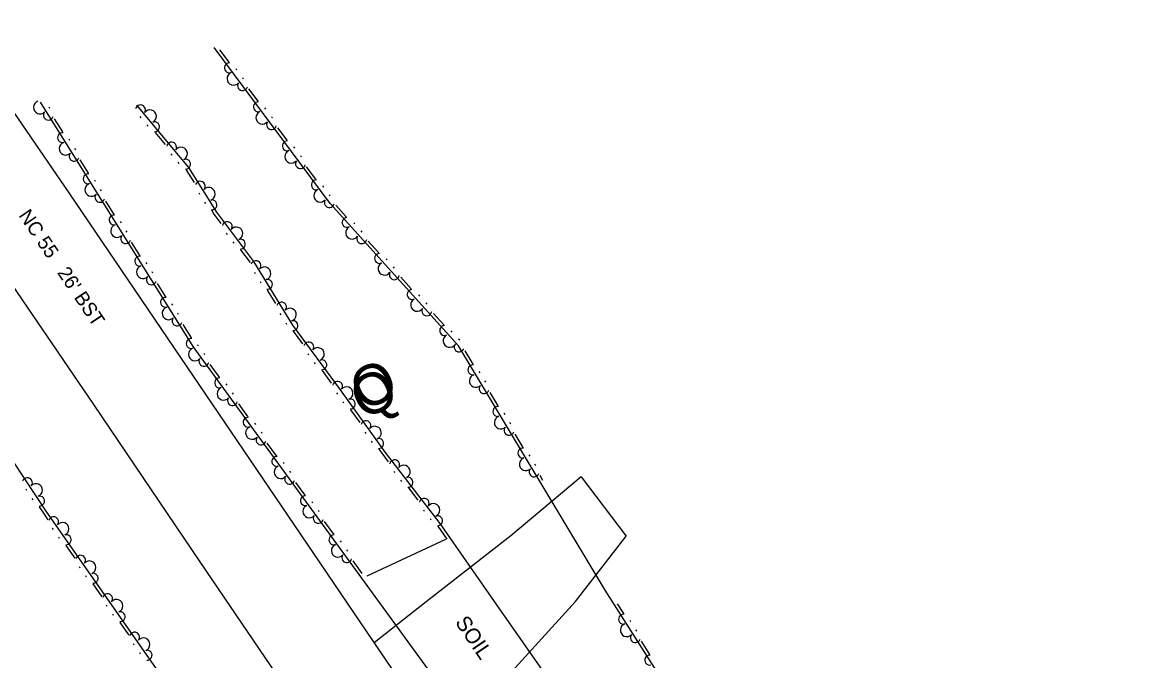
# Model space of a CAD drawing. Extents: x 2030130 to 2036320, y 723205 to 762423.
# Drawn here: x 2032827.6 to 2033121.2, y 761944.8 to 762111.9 of the extents above; entities that cross this region are included whole.
import ezdxf

# ---------------------------------------------------------------- set-up
doc = ezdxf.new("R2010")
doc.units = 0
for name, color, linetype in [('Draft_Station Cardinal Points', 7, 'Continuous'), ('Draft_Station Labels Major', 7, 'Continuous'), ('Draft_Station Tics Major', 7, 'Continuous'), ('Old_Level_15', 7, 'Continuous'), ('Old_Level_23', 7, 'Continuous')]:
    doc.layers.add(name, color=color, linetype=linetype)

msp = doc.modelspace()

# ---------------------------------------------------------------- linework, layer by layer
at = {"layer": 'Draft_Station Labels Major'}
for p, q in [((2032973.91, 761992.92), (2032985.71, 761977.44)), ((2032933.32, 761960.17), (2032919.77, 761949.48))]:
    msp.add_line(p, q, dxfattribs=at)
for points in [[(2032982.25, 761857.44), (2032953.98, 761899.13), (2032895.43, 761985.31), (2032867.48, 762026.64), (2032839.86, 762067.31), (2032810.94, 762109.31), (2032783.52, 762149.89), (2032755.69, 762190.54), (2032727.21, 762232.52), (2032699.29, 762273.24), (2032670.84, 762315.05), (2032643.99, 762354.39), (2032615.89, 762395.7), (2032597.19, 762422.99)], [(2032578.53, 762404.38), (2032622.03, 762340.46), (2032649.81, 762299.71), (2032677.92, 762258.76), (2032706.15, 762217.66), (2032734.05, 762176.43), (2032762.1, 762135.36), (2032790.25, 762094.19), (2032818.14, 762052.99), (2032846.2, 762011.84), (2032874.09, 761970.67), (2032902.04, 761929.59), (2032931.85, 761885.67), (2032959.96, 761844.28)], [(2032973.91, 761992.92), (2032955.52, 761977.52), (2032933.32, 761960.17)], [(2032951.33, 761937.1), (2032972.48, 761960.26), (2032985.71, 761977.44)]]:
    msp.add_lwpolyline(points, dxfattribs=at)
at = {"layer": 'Draft_Station Tics Major'}
msp.add_line((2032938.43, 761976.49), (2032917.81, 761966.94), dxfattribs=at)
for points in [[(2033121.18, 761743.95), (2033080.74, 761813.47), (2033046.05, 761862.02), (2033015.65, 761907.58), (2032980.17, 761963.3), (2032941.81, 762027.2), (2032908.21, 762064.45), (2032877.87, 762105.34)], [(2032881.77, 762101.46), (2032879.32, 762104.75)], [(2032883.81, 762099.4), (2032883.56, 762099.72)], [(2032885.52, 762097.09), (2032885.27, 762097.42)], [(2032889.34, 762091.25), (2032886.9, 762094.54)], [(2033107.4, 761688.4), (2033049.51, 761771.21), (2032985.52, 761870.07), (2032934.46, 761941.71), (2032872.35, 762027.01), (2032832.35, 762090.98)], [(2032834.82, 762089.34), (2032834.61, 762089.69)], [(2032857.5, 762090.26), (2032871.14, 762073.87), (2032878.45, 762062.18), (2032888.1, 762049.28), (2032898.38, 762032.64), (2032910.79, 762015.75), (2032922.64, 761999.26), (2032936.88, 761980.71), (2032951.77, 761959.4), (2032965.55, 761939.68), (2032981.68, 761910.94), (2032991.86, 761892.63), (2033007.03, 761869.02), (2033018.32, 761853.44), (2033031.66, 761833.88), (2033047.89, 761810.12), (2033068.77, 761781.86), (2033086.33, 761752.31)], [(2032891.38, 762089.19), (2032891.14, 762089.52)], [(2032838.17, 762083.21), (2032836, 762086.69)], [(2032858.39, 762087.27), (2032858.65, 762086.95)], [(2032860.22, 762085.06), (2032860.49, 762084.74)], [(2032893.09, 762086.88), (2032892.85, 762087.21)], [(2032862.38, 762083.11), (2032865, 762079.96)], [(2032896.92, 762081.04), (2032894.48, 762084.33)], [(2032840.04, 762080.99), (2032839.83, 762081.34)], [(2032841.57, 762078.56), (2032841.35, 762078.91)], [(2032898.96, 762078.97), (2032898.72, 762079.3)], [(2032844.92, 762072.43), (2032842.74, 762075.91)], [(2032866.52, 762077.49), (2032866.78, 762077.18)], [(2032900.67, 762076.67), (2032900.43, 762077)], [(2032868.36, 762075.29), (2032868.62, 762074.97)], [(2032870.44, 762073.43), (2032872.62, 762069.96)], [(2032904.49, 762070.83), (2032902.05, 762074.12)], [(2032846.79, 762070.21), (2032846.57, 762070.56)], [(2032848.31, 762067.78), (2032848.09, 762068.13)], [(2032873.79, 762067.31), (2032874.01, 762066.96)], [(2032906.53, 762068.77), (2032906.29, 762069.1)], [(2032851.66, 762061.65), (2032849.48, 762065.13)], [(2032875.32, 762064.87), (2032875.53, 762064.52)], [(2032908.24, 762066.46), (2032908, 762066.79)], [(2032912.42, 762061), (2032909.67, 762064.05)], [(2032877.19, 762062.66), (2032877.78, 762061.71), (2032879.61, 762059.26)], [(2032987.59, 761762.73), (2032957.8, 761805.4), (2032921.13, 761858.06), (2032890.88, 761904.34), (2032862.59, 761942.95), (2032834.05, 761983.65), (2032801.35, 762033.01), (2032781.96, 762059.34)], [(2032853.53, 762059.44), (2032853.31, 762059.78)], [(2032914.65, 762059.15), (2032914.37, 762059.45)], [(2032855.05, 762057), (2032854.83, 762057.35)], [(2032881, 762056.72), (2032881.24, 762056.39)], [(2032916.57, 762057.01), (2032916.3, 762057.32)], [(2032858.4, 762050.87), (2032856.22, 762054.35)], [(2032882.72, 762054.42), (2032882.96, 762054.09)], [(2032884.77, 762052.37), (2032887.22, 762049.08)], [(2032920.94, 762051.56), (2032918.19, 762054.61)], [(2032923.16, 762049.71), (2032922.89, 762050.01)], [(2032860.27, 762048.66), (2032860.05, 762049.01)], [(2032861.79, 762046.22), (2032861.57, 762046.57)], [(2032888.37, 762046.5), (2032888.58, 762046.15)], [(2032925.08, 762047.58), (2032924.81, 762047.88)], [(2032865.14, 762040.09), (2032862.96, 762043.57)], [(2032889.88, 762044.06), (2032890.09, 762043.71)], [(2032929.45, 762042.12), (2032926.7, 762045.17)], [(2032891.73, 762041.83), (2032893.89, 762038.34)], [(2032931.68, 762040.27), (2032931.4, 762040.57)], [(2032867.01, 762037.88), (2032866.79, 762038.23)], [(2032933.6, 762038.14), (2032933.33, 762038.44)], [(2032868.53, 762035.44), (2032868.31, 762035.79)], [(2032895.05, 762035.69), (2032895.26, 762035.34)], [(2032937.97, 762032.68), (2032935.22, 762035.73)], [(2032871.88, 762029.32), (2032869.7, 762032.79)], [(2032896.56, 762033.24), (2032896.77, 762032.9)], [(2032898.54, 762031.03), (2032900.97, 762027.72)], [(2032940.19, 762030.83), (2032939.92, 762031.13)], [(2032942.12, 762028.7), (2032941.84, 762029)], [(2032873.74, 762027.2), (2032873.5, 762027.53)], [(2032945.64, 762022.42), (2032943.52, 762025.94)], [(2032875.43, 762024.88), (2032875.19, 762025.21)], [(2032902.34, 762025.17), (2032902.59, 762024.83)], [(2032904.04, 762022.85), (2032904.29, 762022.52)], [(2032879.2, 762019), (2032876.79, 762022.31)], [(2032906.07, 762020.78), (2032908.5, 762017.48)], [(2032947.46, 762020.17), (2032947.25, 762020.52)], [(2032881.22, 762016.92), (2032880.98, 762017.25)], [(2032948.94, 762017.71), (2032948.73, 762018.06)], [(2032882.91, 762014.6), (2032882.67, 762014.93)], [(2032909.86, 762014.93), (2032910.1, 762014.6)], [(2032952.18, 762011.52), (2032950.07, 762015.04)], [(2032886.68, 762008.72), (2032884.27, 762012.04)], [(2032911.54, 762012.6), (2032911.78, 762012.27)], [(2032913.55, 762010.51), (2032915.94, 762007.18)], [(2032954.01, 762009.27), (2032953.8, 762009.62)], [(2032888.71, 762006.64), (2032888.46, 762006.97)], [(2032955.49, 762006.81), (2032955.28, 762007.16)], [(2032890.39, 762004.32), (2032890.15, 762004.65)], [(2032917.28, 762004.61), (2032917.52, 762004.28)], [(2032918.96, 762002.28), (2032919.2, 762001.94)], [(2032958.72, 762000.62), (2032956.61, 762004.14)], [(2032894.17, 761998.44), (2032891.75, 762001.76)], [(2032920.96, 762000.18), (2032921.98, 761998.77), (2032923.43, 761996.88)], [(2032896.19, 761996.37), (2032895.95, 761996.7)], [(2032960.55, 761998.37), (2032960.34, 761998.72)], [(2032897.88, 761994.05), (2032897.63, 761994.38)], [(2032924.86, 761994.35), (2032925.1, 761994.03)], [(2032962.03, 761995.91), (2032961.82, 761996.26)], [(2032901.65, 761988.17), (2032899.24, 761991.48)], [(2032926.61, 761992.07), (2032926.86, 761991.75)], [(2032963.91, 761991.99), (2032963.16, 761993.24)], [(2032828.81, 761989.33), (2032828.58, 761989.68)], [(2032928.68, 761990.05), (2032931.18, 761986.79)], [(2032830.4, 761986.94), (2032830.17, 761987.28)], [(2032834.41, 761981.71), (2032833.37, 761983.19), (2032832.1, 761985.12)], [(2032903.67, 761986.09), (2032903.43, 761986.42)], [(2032905.36, 761983.77), (2032905.12, 761984.1)], [(2032932.6, 761984.27), (2032932.85, 761983.94)], [(2032934.35, 761981.99), (2032934.6, 761981.67)], [(2032835.73, 761979.12), (2032835.49, 761979.46)], [(2032909.13, 761977.89), (2032906.72, 761981.2)], [(2032936.39, 761979.98), (2032938.74, 761976.62)], [(2032837.37, 761976.77), (2032837.14, 761977.11)], [(2032911.15, 761975.81), (2032910.91, 761976.14)], [(2032841.48, 761971.63), (2032839.12, 761974.99)], [(2032912.84, 761973.49), (2032912.6, 761973.82)], [(2032916.61, 761967.61), (2032914.2, 761970.93)], [(2032842.79, 761969.05), (2032842.55, 761969.38)], [(2032844.44, 761966.69), (2032844.2, 761967.03)], [(2032848.54, 761961.56), (2032846.18, 761964.92)], [(2032849.85, 761958.97), (2032849.62, 761959.31)], [(2032985.06, 761957.15), (2032983.43, 761959.71)], [(2032851.5, 761956.62), (2032851.26, 761956.96)], [(2032986.95, 761954.95), (2032986.73, 761955.29)], [(2032855.6, 761951.48), (2032853.25, 761954.84)], [(2032988.49, 761952.53), (2032988.27, 761952.87)], [(2032991.89, 761946.43), (2032989.69, 761949.89)], [(2032856.91, 761948.9), (2032856.68, 761949.23)], [(2032858.56, 761946.55), (2032858.33, 761946.88)]]:
    msp.add_lwpolyline(points, dxfattribs=at)
for centre, radius, start, end in [((2032881.84, 762099.98), 1.3, 87.344, 288.1405), ((2032882.89, 762097.18), 1.69, 112.5392, 320.6117), ((2032885.26, 762095.37), 1.3, 145.0104, 345.807), ((2032832.22, 762089.64), 1.69, 107.9852, 316.0577), ((2032889.42, 762089.77), 1.3, 87.344, 288.1405), ((2032834.43, 762087.64), 1.3, 140.4564, 341.253), ((2032858.55, 762089), 1.3, 328.2038, 169.0004), ((2032861.01, 762087.32), 1.69, 295.7326, 143.8051), ((2032890.47, 762086.98), 1.69, 112.5392, 320.6117), ((2032862.22, 762084.59), 1.3, 270.5374, 111.3339), ((2032892.84, 762085.16), 1.3, 145.0104, 345.807), ((2032838.13, 762081.73), 1.3, 82.79, 283.5865), ((2032838.96, 762078.86), 1.69, 107.9852, 316.0577), ((2032866.68, 762079.23), 1.3, 328.2038, 169.0004), ((2032869.15, 762077.54), 1.69, 295.7326, 143.8051), ((2032896.99, 762079.56), 1.3, 87.344, 288.1405), ((2032841.18, 762076.86), 1.3, 140.4564, 341.253), ((2032870.35, 762074.81), 1.3, 270.5374, 111.3339), ((2032898.05, 762076.77), 1.69, 112.5392, 320.6117), ((2032900.42, 762074.95), 1.3, 145.0104, 345.807), ((2032844.87, 762070.95), 1.3, 82.79, 283.5865), ((2032874.18, 762069), 1.3, 320.4692, 161.2658), ((2032904.57, 762069.35), 1.3, 87.344, 288.1405), ((2032845.7, 762068.08), 1.69, 107.9852, 316.0577), ((2032847.92, 762066.09), 1.3, 140.4564, 341.253), ((2032876.4, 762067), 1.69, 287.998, 136.0705), ((2032905.62, 762066.56), 1.69, 112.5392, 320.6117), ((2032877.23, 762064.13), 1.3, 262.8028, 103.5993), ((2032907.99, 762064.74), 1.3, 145.0104, 345.807), ((2032851.61, 762060.17), 1.3, 82.79, 283.5865), ((2032852.44, 762057.31), 1.69, 107.9852, 316.0577), ((2032881.25, 762058.44), 1.3, 325.2249, 166.0215), ((2032883.62, 762056.63), 1.69, 292.7537, 140.8262), ((2032912.63, 762059.54), 1.3, 92.823, 293.6195), ((2032913.95, 762056.86), 1.69, 118.0182, 326.0907), ((2032854.66, 762055.31), 1.3, 140.4564, 341.253), ((2032884.69, 762053.84), 1.3, 267.5584, 108.355), ((2032916.48, 762055.28), 1.3, 150.4894, 351.286), ((2032858.35, 762049.4), 1.3, 82.79, 283.5865), ((2032888.77, 762048.2), 1.3, 320.133, 160.9295), ((2032921.15, 762050.1), 1.3, 92.823, 293.6195), ((2032859.18, 762046.53), 1.69, 107.9852, 316.0577), ((2032890.97, 762046.19), 1.69, 287.6618, 135.7342), ((2032922.46, 762047.42), 1.69, 118.0182, 326.0907), ((2032925, 762045.84), 1.3, 150.4894, 351.286), ((2032861.4, 762044.53), 1.3, 140.4564, 341.253), ((2032891.78, 762043.31), 1.3, 262.4665, 103.2631), ((2032929.67, 762040.66), 1.3, 92.823, 293.6195), ((2032865.09, 762038.62), 1.3, 82.79, 283.5865), ((2032895.45, 762037.38), 1.3, 320.133, 160.9295), ((2032930.98, 762037.98), 1.69, 118.0182, 326.0907), ((2032865.92, 762035.75), 1.69, 107.9852, 316.0577), ((2032868.14, 762033.75), 1.3, 140.4564, 341.253), ((2032897.65, 762035.37), 1.69, 287.6618, 135.7342), ((2032933.51, 762036.4), 1.3, 150.4894, 351.286), ((2032898.48, 762032.5), 1.3, 267.0923, 107.8889), ((2032938.18, 762031.22), 1.3, 92.823, 293.6195), ((2032871.84, 762027.84), 1.3, 82.79, 283.5865), ((2032939.5, 762028.54), 1.69, 118.0182, 326.0907), ((2032872.81, 762025), 1.69, 112.021, 320.0935), ((2032902.61, 762026.89), 1.3, 324.7588, 165.5554), ((2032904.97, 762025.06), 1.69, 292.2876, 140.3601), ((2032941.98, 762026.92), 1.3, 139.4145, 340.2111), ((2032875.16, 762023.16), 1.3, 144.4922, 345.2888), ((2032906.01, 762022.26), 1.3, 267.0923, 107.8889), ((2032945.57, 762020.94), 1.3, 81.748, 282.5446), ((2032879.26, 762017.52), 1.3, 86.8257, 287.6223), ((2032910.14, 762016.64), 1.3, 324.7588, 165.5554), ((2032946.34, 762018.06), 1.69, 106.9433, 315.0158), ((2032880.29, 762014.72), 1.69, 112.021, 320.0935), ((2032912.49, 762014.8), 1.69, 291.6551, 139.7275), ((2032948.52, 762016.02), 1.3, 139.4145, 340.2111), ((2032882.64, 762012.88), 1.3, 144.4922, 345.2888), ((2032913.5, 762011.99), 1.3, 266.4598, 107.2564), ((2032952.11, 762010.04), 1.3, 81.748, 282.5446), ((2032886.74, 762007.24), 1.3, 86.8257, 287.6223), ((2032952.88, 762007.16), 1.69, 106.9433, 315.0158), ((2032887.77, 762004.44), 1.69, 112.021, 320.0935), ((2032917.56, 762006.32), 1.3, 324.1263, 164.9228), ((2032919.9, 762004.47), 1.69, 291.6551, 139.7275), ((2032955.06, 762005.12), 1.3, 139.4145, 340.2111), ((2032890.12, 762002.6), 1.3, 144.4922, 345.2888), ((2032920.91, 762001.66), 1.3, 266.4598, 107.2564), ((2032958.65, 761999.15), 1.3, 81.748, 282.5446), ((2032894.23, 761996.97), 1.3, 86.8257, 287.6223), ((2032925.08, 761996.08), 1.3, 325.9561, 166.7527), ((2032959.43, 761996.26), 1.69, 106.9433, 315.0158), ((2032895.25, 761994.16), 1.69, 112.021, 320.0935), ((2032927.48, 761994.3), 1.69, 293.4849, 141.5574), ((2032961.61, 761994.22), 1.3, 139.4145, 340.2111), ((2032828.93, 761991.38), 1.3, 321.9615, 162.758), ((2032831.2, 761989.44), 1.69, 289.4903, 137.5628), ((2032897.61, 761992.32), 1.3, 144.4922, 345.2888), ((2032928.58, 761991.52), 1.3, 268.2896, 109.0862), ((2032832.1, 761986.59), 1.3, 264.295, 105.0916), ((2032901.71, 761986.69), 1.3, 86.8257, 287.6223), ((2032902.74, 761983.88), 1.69, 112.021, 320.0935), ((2032932.83, 761985.99), 1.3, 325.9561, 166.7527), ((2032935.22, 761984.22), 1.69, 293.4849, 141.5574), ((2032835.79, 761981.17), 1.3, 323.4676, 164.2641), ((2032905.09, 761982.05), 1.3, 144.4922, 345.2888), ((2032936.32, 761981.44), 1.3, 268.2896, 109.0862), ((2032838.11, 761979.29), 1.69, 290.9964, 139.0688), ((2032839.09, 761976.47), 1.3, 265.8011, 106.5977), ((2032909.19, 761976.41), 1.3, 86.8257, 287.6223), ((2032910.22, 761973.61), 1.69, 112.021, 320.0935), ((2032842.85, 761971.1), 1.3, 323.4676, 164.2641), ((2032845.17, 761969.22), 1.69, 290.9964, 139.0688), ((2032912.57, 761971.77), 1.3, 144.4922, 345.2888), ((2032846.15, 761966.39), 1.3, 265.8011, 106.5977), ((2032849.92, 761961.02), 1.3, 323.4676, 164.2641), ((2032852.24, 761959.14), 1.69, 290.9964, 139.0688), ((2032853.21, 761956.32), 1.3, 265.8011, 106.5977), ((2032985.03, 761955.67), 1.3, 83.2553, 284.0518), ((2032985.88, 761952.81), 1.69, 108.4506, 316.523), ((2032856.98, 761950.95), 1.3, 323.4676, 164.2641), ((2032859.3, 761949.07), 1.69, 290.9964, 139.0688), ((2032988.12, 761950.83), 1.3, 140.9217, 341.7183), ((2032860.27, 761946.25), 1.3, 265.8011, 106.5977), ((2032991.86, 761944.95), 1.3, 83.2553, 284.0518)]:
    msp.add_arc(centre, radius, start, end, dxfattribs=at)

# ---------------------------------------------------------------- texts
at = {"layer": 'Draft_Station Cardinal Points'}
msp.add_text('O', height=10.66, rotation=25.7434, dxfattribs=at).set_placement((2032916.84, 762009.91))
at = {"layer": 'Old_Level_15'}
msp.add_text('Q', height=10.66, rotation=25.7434, dxfattribs=at).set_placement((2032916.84, 762007.68))
at = {"layer": 'Old_Level_23'}
for s, height, rotation, p in [("NC 55   26' BST", 3.6909, 304.0128, (2032826.5, 762061.37)), ('SOIL', 4, 304.1672, (2032940.78, 761954.84))]:
    msp.add_text(s, height=height, rotation=rotation, dxfattribs=at).set_placement(p)

doc.saveas('drawing.dxf')
